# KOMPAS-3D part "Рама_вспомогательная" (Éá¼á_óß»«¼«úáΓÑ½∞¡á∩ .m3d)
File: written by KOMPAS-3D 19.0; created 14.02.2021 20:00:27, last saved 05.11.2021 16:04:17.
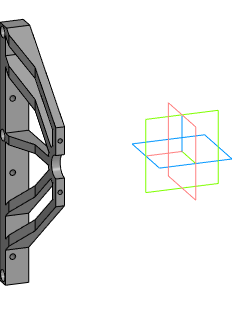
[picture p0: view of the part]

Document properties: Автор: Agent Smith; Полное имя файла: D:\3D_print\3D проекты Компас 3D\Халява Projects 5\Рама_вспомогательная .m3d

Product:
- Part/product: Рама_вспомогательная
    Масса: 0.367054

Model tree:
1. Эскиз:1  (with: Элемент выдавливания:1, Элемент выдавливания:9)
2. Элемент выдавливания:1
     Расстояние 2 = 6
3. Эскиз:2  (with: Элемент выдавливания:1, Элемент выдавливания:11, Элемент выдавливания:16)
4. Элемент выдавливания:2
     Расстояние 1 = 10
5. Уклон:1  (with: Элемент выдавливания:1, Элемент выдавливания:2)
     Угол уклона = -65
6. Эскиз:3  (with: Элемент выдавливания:1, Элемент выдавливания:2, Элемент выдавливания:17)
7. Элемент выдавливания:3  (with: Элемент выдавливания:1)
     Расстояние 2 = 6
8. Эскиз:4  (with: Элемент выдавливания:1, Элемент выдавливания:13)
9. Элемент выдавливания:4  (with: Элемент выдавливания:1)
     Расстояние 2 = 6
10. Эскиз:5  (with: Элемент выдавливания:1, Элемент выдавливания:12, Элемент выдавливания:2)
11. Элемент выдавливания:5  (with: Элемент выдавливания:1)
     Расстояние 2 = 10

Referenced files in D:\3D_print\3D проекты Компас 3D\Редуктор (Снова)\: Намоточный станок (Projects 6).a3d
